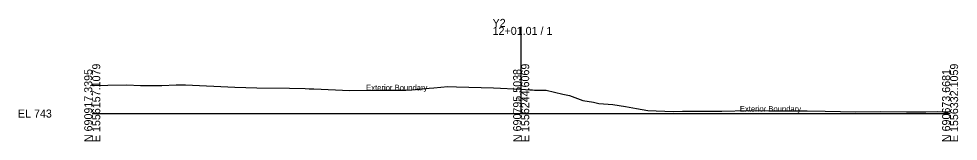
# Model space of a CAD drawing. Extents: x -26 to 303, y -10 to 5027.
# Drawn here: x -25.7 to 302.8, y 2490.3 to 2533.2 of the extents above; entities that cross this region are included whole.
import ezdxf

# ---------------------------------------------------------------- set-up
doc = ezdxf.new("R2010")
doc.units = 0
for name, color, linetype in [('Default', 7, 'Continuous'), ('Exist Cross Section Cell', 7, 'Continuous'), ('Exist XS Center Line Elevation Label', 7, 'Continuous'), ('Exist XS Ground Line', 7, 'Continuous')]:
    doc.layers.add(name, color=color, linetype=linetype)

msp = doc.modelspace()

# ---------------------------------------------------------------- linework, layer by layer
at = {"layer": 'Exist Cross Section Cell'}
for p, q in [((150, 2500), (150, 2530.36)), ((0, 2500), (150, 2500)), ((150, 2500), (300, 2500))]:
    msp.add_line(p, q, dxfattribs=at)
at = {"layer": 'Exist XS Ground Line'}
msp.add_lwpolyline([(0, 2509.85), (5.45, 2509.9), (12.07, 2510.01), (16.83, 2509.86), (19.49, 2509.86), (24.38, 2509.84), (29.31, 2510.12), (32.6, 2510.05), (49.92, 2509.26), (57.52, 2509.02), (69.01, 2508.93), (74.5, 2508.81), (75.91, 2508.68), (77.48, 2508.61), (90.09, 2508.09), (99.3, 2508.18), (101.08, 2508.19), (109.71, 2508.15), (111.79, 2508.3), (117.83, 2508.87), (119.42, 2509.05), (124.37, 2509.44), (127.42, 2509.32), (140.32, 2508.98), (150, 2508.49), (153.05, 2508.35), (153.93, 2508.26), (154.7, 2508.18), (157.57, 2508.16), (158.73, 2508.15), (164.52, 2506.83), (166.95, 2506.38), (171.62, 2504.56), (175.27, 2503.94), (177.14, 2503.5), (182.07, 2503.12), (186.47, 2502.52), (190.34, 2501.81), (194.27, 2501.08), (203.18, 2500.67), (206.45, 2500.79), (207.32, 2500.79), (220.19, 2500.88), (229.37, 2501.12), (236.6, 2501.01), (241.86, 2500.94), (250.07, 2500.98), (256.34, 2500.8), (266.99, 2500.58), (275.67, 2500.7), (284.8, 2500.65), (291.47, 2500.62), (295.65, 2500.75), (300, 2500.65)], dxfattribs=at)

# ---------------------------------------------------------------- texts
at = {"layer": 'Default'}
for s, height, p in [('Exterior Boundary', 2, (95.78, 2508.1)), ('Exterior Boundary', 2, (226.48, 2500.66)), ('-', 0.0001, (0, 2500)), ('-', 0.0001, (0, 2500))]:
    msp.add_text(s, height=height, dxfattribs=at).set_placement(p)
at = {"layer": 'Exist Cross Section Cell'}
for s, p in [('Y2', (140, 2530.36)), ('12+01.01 / 1', (140, 2527.56)), ('EL 743', (-26, 2498.6))]:
    msp.add_text(s, height=2.8, dxfattribs=at).set_placement(p)
for s, p in [('E 1556157.1079', (2.8, 2490)), ('E 1556244.6069', (152.8, 2490)), ('E 1556332.1059', (302.8, 2490)), ('N 690917.3395', (0, 2490)), ('N 690795.5038', (150, 2490)), ('N 690673.6681', (300, 2490))]:
    msp.add_text(s, height=2.8, rotation=90, dxfattribs=at).set_placement(p)
at = {"layer": 'Exist XS Center Line Elevation Label'}
msp.add_text('751.49', height=1, dxfattribs=at).set_placement((148.03, 2504.49))

doc.saveas('drawing.dxf')
